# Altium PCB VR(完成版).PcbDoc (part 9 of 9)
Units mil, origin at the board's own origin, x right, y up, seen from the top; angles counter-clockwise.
Board outline 2839.68 x 2020.7 mil, 6 copper layers (TOP, GND02, SIN03, SIN04, PWR05, BOTTOM); 494 components, 404 nets, 7124 pads, 1123 vias.
Unrouted connection lines stored in the file: 10.
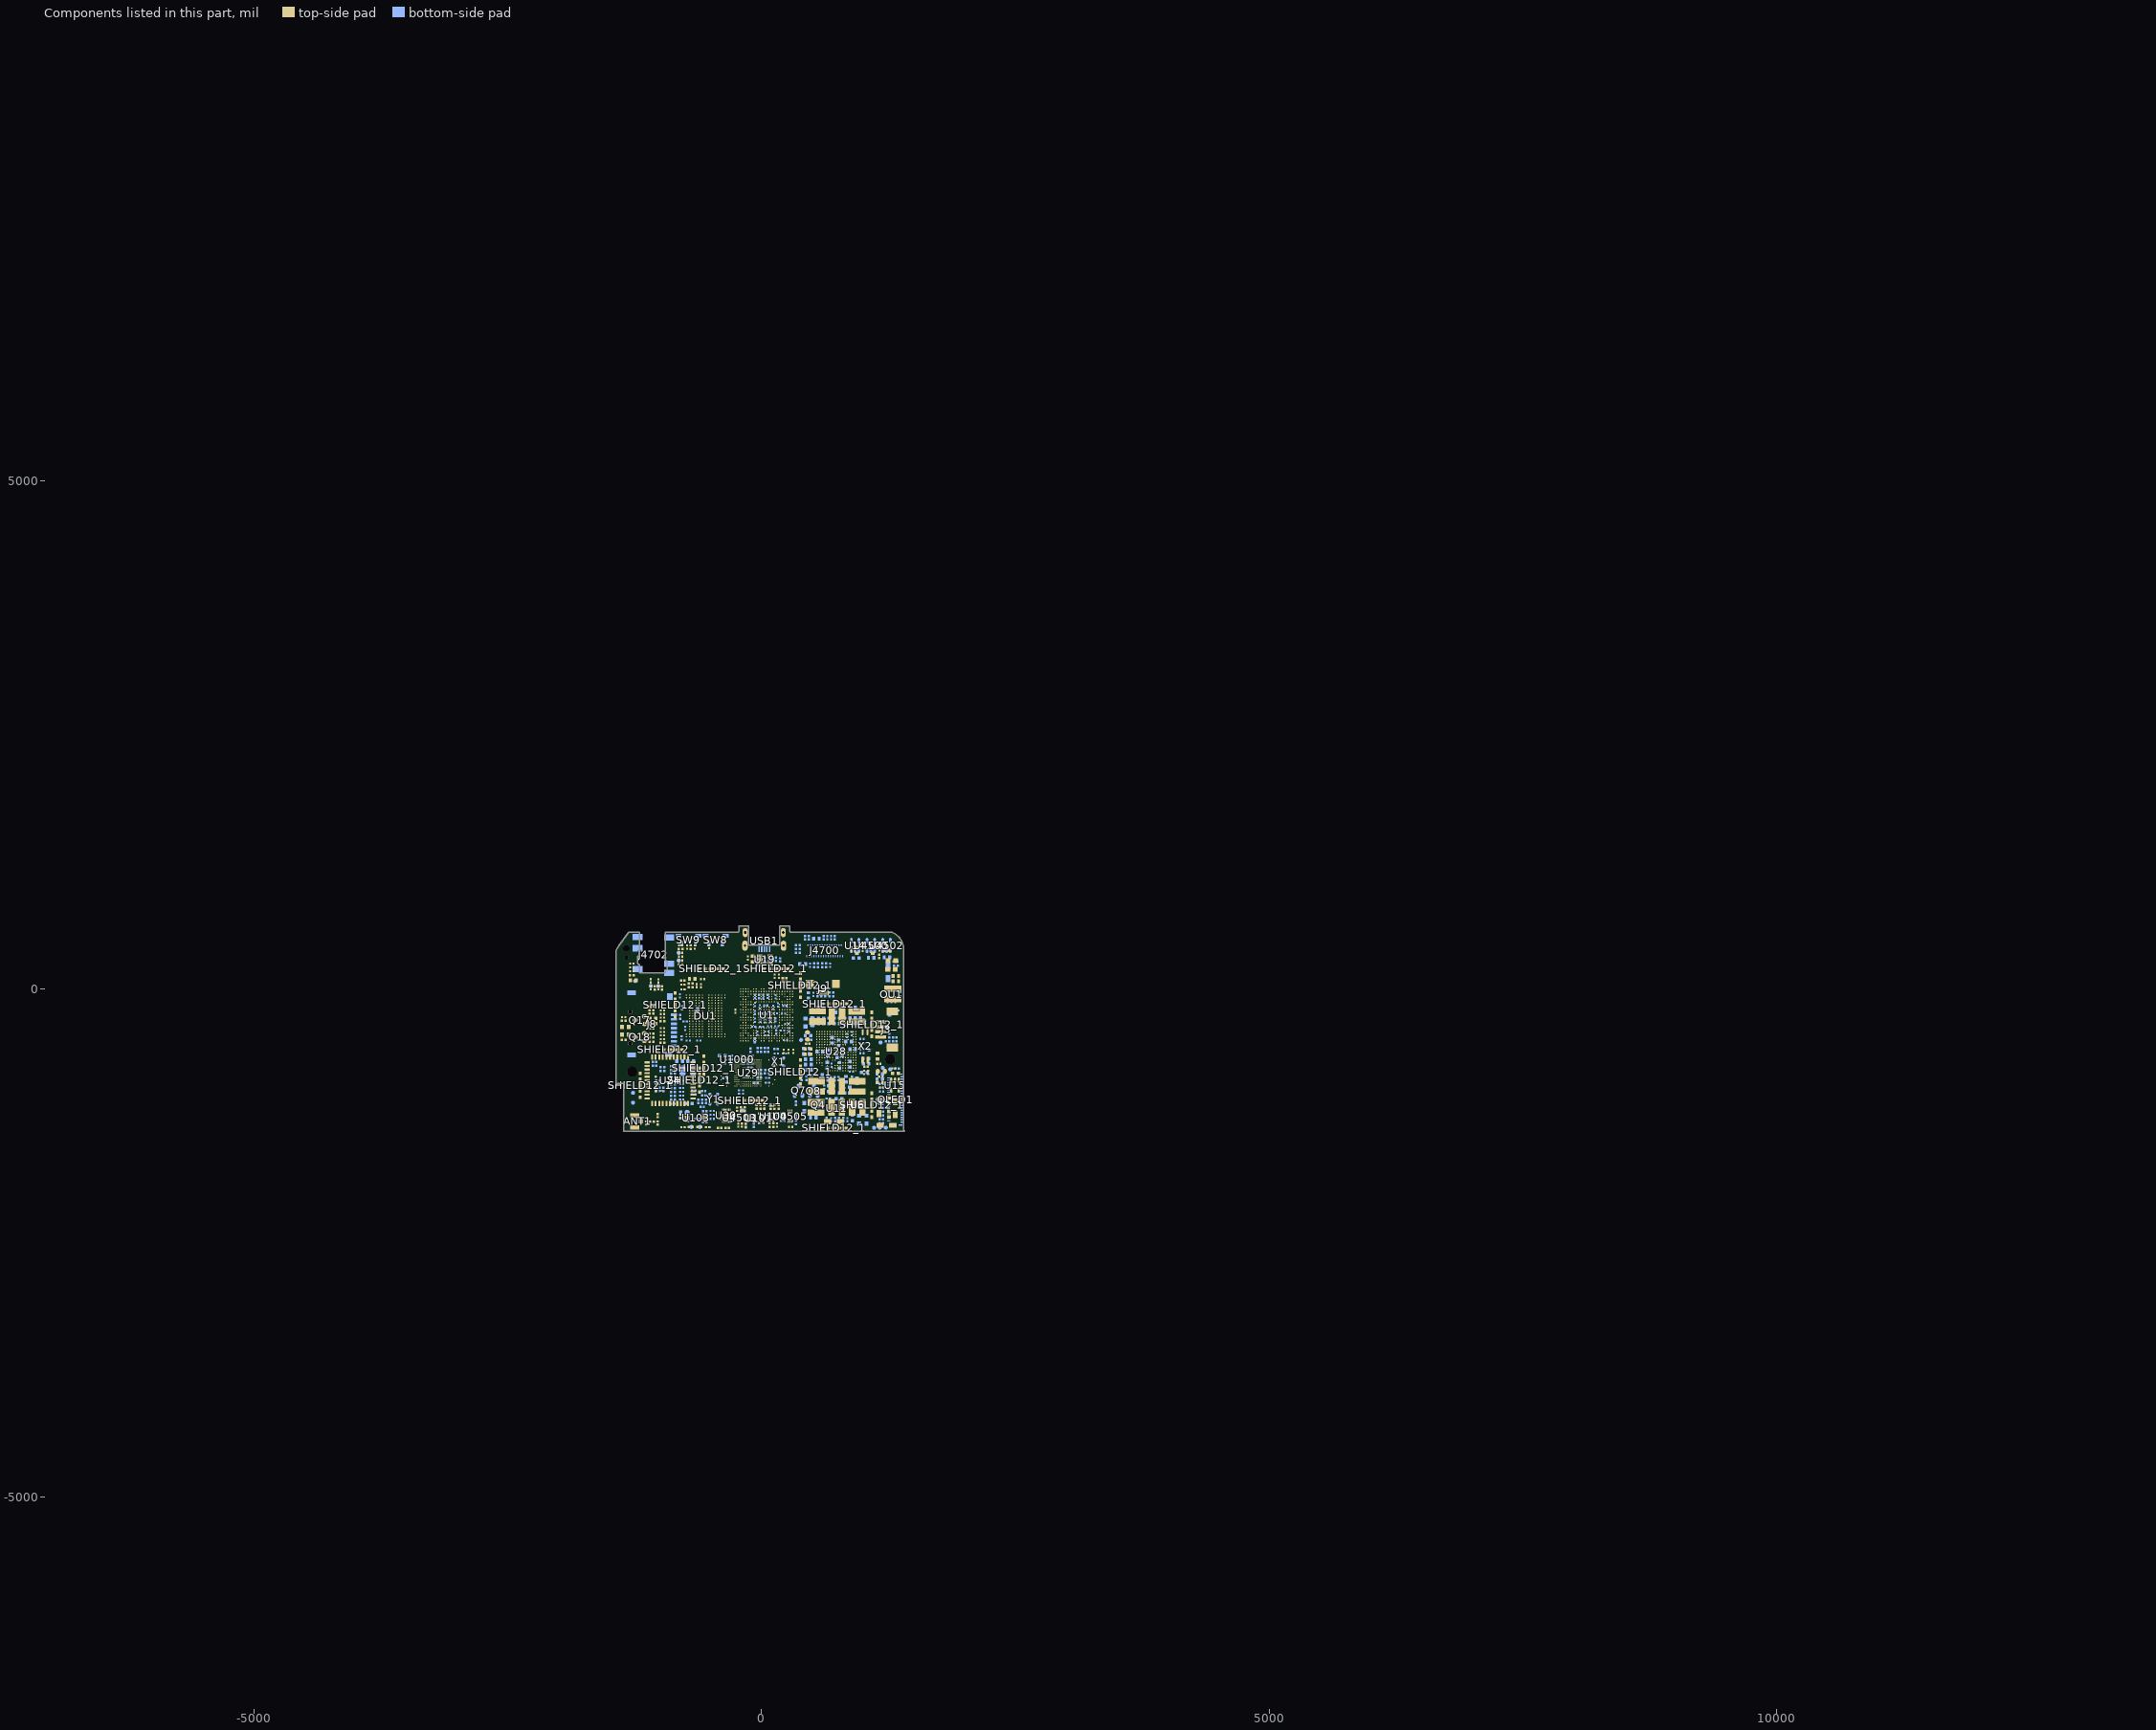
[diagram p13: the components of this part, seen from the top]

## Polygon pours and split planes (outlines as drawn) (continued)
VBAT on BOTTOM "Top Layer-No Net" (hatched 90Degree grid 4 track 5, remove dead copper, pour order 1004): -862,-1364 -862,-1199 -900,-1199 -927,-1172 -927,-1056.59 -924.27,-1053.86 -954.13,-1024 -1143,-1024 -1208.14,-958.86 -1303,-958.86 -1303,-1067 -994,-1067 -965,-1096 -965,-1329 -930,-1364
VBAT on BOTTOM "Top Layer-No Net" (hatched 90Degree grid 4 track 5, remove dead copper, pour order 1002): -1236,-1048 -1236,-954 -1251,-954 -1308,-954 -1308,-1002 -1308,-1048 -1236,-1048
USBVBUS on BOTTOM "Top Layer-No Net" (hatched 90Degree grid 4 track 5, remove dead copper, pour order 1006): 425,-346.86 524.73,-346.86 524.73,-399.15 545.73,-420.15 545.73,-437.86 544.73,-437.86 536.73,-445.86 460.86,-445.86 425,-410
GND on BOTTOM "Top Layer-No Net" (hatched 90Degree grid 4 track 5, remove dead copper, pour order 1003): 17 vertices, not listed, extent 490,-318.86 1046.73,-193.86
VCC_TP on BOTTOM "Top Layer-No Net" (hatched 90Degree grid 4 track 5, remove dead copper, pour order 1013): 456.73,16.14 518.73,16.14 518.73,-31.86 518.73,-44.86 462.73,-44.86 456.73,-44.86 456.73,16.14
DCDC1 on BOTTOM "Top Layer-No Net" (hatched 90Degree grid 4 track 5, remove dead copper, pour order 1012): 406.73,39.14 406.73,85.14 425.73,85.14 474.73,85.14 474.73,48.14 474.73,39.14 406.73,39.14
USB-5V on BOTTOM "Top Layer-No Net" (hatched 90Degree grid 4 track 5, remove dead copper, pour order 1011): 1229.73,256.14 1333.73,256.14 1333.73,217.14 1333.73,40.14 1301.73,40.14 1286.73,40.14 1286.73,53.14 1286.73,164.14 1264.73,164.14 1229.73,164.14 1229.73,256.14
N21149589 on BOTTOM "Top Layer-No Net" (hatched 90Degree grid 4 track 5, remove dead copper, pour order 1010): 1222.73,-14.86 1222.73,114.14 1251.73,114.14 1271.73,114.14 1271.73,14.14 1271.73,-14.86 1222.73,-14.86
VCC15_DVP on BOTTOM "Top Layer-No Net" (hatched 90Degree grid 4 track 5, remove dead copper, pour order 1008): 1277.23,496.14 1237.23,496.14 1237.23,478.14 1237.23,458.14 1271.23,458.14 1277.23,458.14 1277.23,496.14
VCC28_DVP on BOTTOM "Top Layer-No Net" (hatched 90Degree grid 4 track 5, remove dead copper, pour order 1007): 1122.73,496.14 1082.73,496.14 1082.73,478.14 1082.73,458.14 1116.73,458.14 1122.73,458.14 1122.73,496.14
VCC18_DVP on BOTTOM "Top Layer-No Net" (hatched 90Degree grid 4 track 5, remove dead copper, pour order 1006): 968.73,492.14 928.73,492.14 928.73,474.14 928.73,454.14 962.73,454.14 968.73,454.14 968.73,492.14
DCDC1 on BOTTOM "Top Layer-No Net" (hatched 90Degree grid 4 track 5, remove dead copper, pour order 1005): 1253.73,392.58 1311.73,392.58 1311.73,354.58 1311.73,296.58 1266.73,296.58 1253.73,296.58 1253.73,392.58
DCDC1 on BOTTOM "Top Layer-No Net" (hatched 90Degree grid 4 track 5, remove dead copper, pour order 1004): 1098.73,388.14 1156.73,388.14 1156.73,350.14 1156.73,292.14 1111.73,292.14 1098.73,292.14 1098.73,388.14
DCDC1 on BOTTOM "Top Layer-No Net" (hatched 90Degree grid 4 track 5, remove dead copper, pour order 1003): 952.73,388.14 1010.73,388.14 1010.73,350.14 1010.73,292.14 965.73,292.14 952.73,292.14 952.73,388.14
GND on BOTTOM "Top Layer-No Net" (hatched 90Degree grid 4 track 5, remove dead copper, pour order 1002): 78.73,412.14 238.73,412.14 238.73,375.14 238.73,355.14 91.73,355.14 74.73,355.14 74.73,399.14 74.73,412.14 78.73,412.14
USBVBUS on BOTTOM "Top Layer-No Net" (hatched 90Degree grid 4 track 5, remove dead copper, pour order 1001): -18.27,413.14 -126.27,413.14 -126.27,302.14 -18.27,302.14
N21107518 on BOTTOM "Top Layer-No Net" (hatched 90Degree grid 4 track 5, remove dead copper, pour order 1000): 18 vertices, not listed, extent -1049.27,-406.86 -832.27,-337.86
BB-VBAT on BOTTOM "Top Layer-No Net" (hatched 90Degree grid 4 track 5, remove dead copper, pour order 1010): -809.27,-1145.86 -790.27,-1126.86 -752.27,-1126.86 -734.27,-1126.86 -734.27,-1140.86 -734.27,-1165.86 -794.27,-1165.86 -809.27,-1165.86 -809.27,-1145.86
N17860913 on BOTTOM "Top Layer-No Net" (hatched 90Degree grid 4 track 5, remove dead copper, pour order 1009): -664.27,-816.86 -725.27,-816.86 -725.27,-784.86 -725.27,-747.86 -709.27,-747.86 -660.27,-747.86 -660.27,-777.86 -660.27,-816.86 -664.27,-816.86
N17861416 on BOTTOM "Top Layer-No Net" (hatched 90Degree grid 4 track 5, remove dead copper, pour order 1008): -794.27,-697.86 -794.27,-818.86 -776.27,-818.86 -754.27,-818.86 -754.27,-758.86 -754.27,-697.86 -794.27,-697.86
PS on BOTTOM "Top Layer-No Net" (hatched 90Degree grid 4 track 5, remove dead copper, pour order 1007): -781.27,-1260.86 -854.27,-1260.86 -854.27,-1279.86 -854.27,-1307.86 -827.27,-1307.86 -781.27,-1307.86 -781.27,-1260.86
N22437840 on BOTTOM "Top Layer-No Net" (hatched 90Degree grid 4 track 5, remove dead copper, pour order 1006): -660.27,-1265.86 -660.27,-1206.86 -682.27,-1206.86 -812.27,-1206.86 -812.27,-1217.86 -812.27,-1227.86 -716.27,-1227.86 -703.27,-1227.86 -703.27,-1258.86 -703.27,-1265.86 -660.27,-1265.86
DCDC1 on BOTTOM "Top Layer-No Net" (hatched 90Degree grid 4 track 5, remove dead copper, pour order 1005): 295.73,-1268.86 348.73,-1268.86 348.73,-1291.86 348.73,-1307.86 335.73,-1307.86 295.73,-1307.86 295.73,-1268.86
PS on BOTTOM "Top Layer-No Net" (hatched 90Degree grid 4 track 5, remove dead copper, pour order 1005): 675.73,-487.86 720.73,-487.86 720.73,-365.86 694.73,-365.86 694.73,-332.86 596.73,-332.86 596.73,-361.86 637.73,-361.86 675.73,-399.86
VDD-CPUB on BOTTOM "Top Layer-No Net" (hatched 90Degree grid 4 track 5, remove dead copper, pour order 1001): 745.73,-206.86 745.73,-177.86 662.73,-177.86 645.73,-177.86 645.73,-243.86 645.73,-261.86 723.73,-261.86 745.73,-261.86 745.73,-206.86
GND on BOTTOM "Top Layer-No Net" (hatched 90Degree grid 4 track 5, remove dead copper, pour order 1007): 447.73,-803.86 447.73,-530.86 423.73,-530.86 403.73,-530.86 403.73,-559.86 403.73,-813.86 435.73,-813.86 447.73,-813.86 447.73,-803.86
PS on BOTTOM "Top Layer-No Net" (hatched 90Degree grid 4 track 5, remove dead copper, pour order 1004): 526.73,-578.86 567.73,-578.86 567.73,-595.86 567.73,-632.86 545.73,-632.86 526.73,-632.86 526.73,-578.86
GND on BOTTOM "Top Layer-No Net" (hatched 90Degree grid 4 track 5, remove dead copper, pour order 1003): 835.73,-896.86 895.73,-896.86 895.73,-919.86 895.73,-984.86 872.73,-984.86 799.73,-984.86 799.73,-937.86 799.73,-918.86 820.73,-918.86 835.73,-918.86 835.73,-896.86
N21179643 on BOTTOM "Top Layer-No Net" (hatched 90Degree grid 4 track 5, remove dead copper, pour order 1002): 902.73,-807.86 890.41,-807.86 890.41,-866.86 890.41,-884.86 948.73,-884.86 957.73,-884.86 957.73,-858.86 957.73,-838.86 933.73,-838.86 926.73,-838.86 926.73,-821.86 926.73,-807.86 902.73,-807.86
N21179643 on BOTTOM "Top Layer-No Net" (hatched 90Degree grid 4 track 5, remove dead copper, pour order 1001): 856.73,-697.86 905.73,-697.86 905.73,-748.86 856.73,-748.86
VLED- on BOTTOM "Top Layer-No Net" (hatched 90Degree grid 4 track 5, remove dead copper, pour order 1001): 1198.73,-942.86 1198.73,-911.86 1238.73,-911.86 1272.73,-911.86 1284.73,-899.86 1290.73,-893.86 1353.73,-893.86 1382.73,-893.86 1382.73,-911.69 1382.73,-918.86 1358.73,-918.86 1297.73,-918.86 1283.73,-932.86 1273.73,-942.86 1198.73,-942.86
LCD_-V50AP on BOTTOM "Top Layer-No Net" (hatched 90Degree grid 4 track 5, remove dead copper, pour order 1000): 1382.73,-975.86 1312.73,-975.86 1312.73,-987.86 1312.73,-997.86 1345.73,-997.86 1382.73,-997.86 1382.73,-975.86
GND on BOTTOM "Top Layer-No Net" (hatched 90Degree grid 4 track 5, remove dead copper, pour order 1000): 1149.73,-899.86 1149.73,-785.86 1112.73,-785.86 1105.73,-785.86 1105.73,-829.86 1105.73,-899.86 1149.73,-899.86
VLED- on BOTTOM "Top Layer-No Net" (hatched 90Degree grid 4 track 5, remove dead copper, pour order 1001): 1188.73,-773.86 1218.73,-773.86 1218.73,-872.86 1218.73,-938.86 1209.73,-938.86 1188.73,-938.86 1188.73,-773.86
N21042265 on BOTTOM "Top Layer-No Net" (hatched 90Degree grid 4 track 5, remove dead copper, pour order 1002): 1167.73,-924.86 1115.73,-924.86 1115.73,-954.86 1115.73,-1010.86 1130.73,-1010.86 1141.73,-1010.86 1141.73,-978.86 1141.73,-947.86 1165.73,-947.86 1167.73,-947.86 1167.73,-924.86
LCD_+V50AP on BOTTOM "Top Layer-No Net" (hatched 90Degree grid 4 track 5, remove dead copper, pour order 1003): 1105.73,-1071.86 1164.73,-1071.86 1164.73,-1140.86 1105.73,-1140.86
DC1-SW on BOTTOM "Top Layer-No Net" (hatched 90Degree grid 4 track 5, remove dead copper, pour order 1004): 859.73,-1256.86 859.73,-1090.86 924.73,-1090.86 924.73,-1256.86
N22015419 on BOTTOM "Top Layer-No Net" (hatched 90Degree grid 4 track 5, remove dead copper, pour order 1005): 978.73,-1105.86 978.73,-1064.86 1003.73,-1064.86 1054.73,-1064.86 1054.73,-1106.86 1054.73,-1112.86 989.73,-1112.86 978.73,-1112.86 978.73,-1105.86
N21042253 on BOTTOM "Top Layer-No Net" (hatched 90Degree grid 4 track 5, remove dead copper, pour order 1006): 760.73,-1109.86 836.73,-1109.86 836.73,-1153.86 760.73,-1153.86
PS on BOTTOM "Top Layer-No Net" (hatched 90Degree grid 4 track 5, remove dead copper, pour order 1007): 664.73,-1068.86 744.73,-1068.86 744.73,-1090.86 744.73,-1110.86 730.73,-1110.86 719.73,-1110.86 719.73,-1134.86 719.73,-1149.86 690.73,-1149.86 664.73,-1149.86 664.73,-1068.86
VLED+ on BOTTOM "Top Layer-No Net" (hatched 90Degree grid 4 track 5, remove dead copper, pour order 1008): 666.73,-1160.86 752.73,-1160.86 752.73,-1181.86 752.73,-1194.86 728.73,-1194.86 666.73,-1194.86 666.73,-1160.86
DCDC1 on BOTTOM "Top Layer-No Net" (hatched 90Degree grid 4 track 5, remove dead copper, pour order 1009): 857.01,-1012.86 966.73,-1012.86 966.73,-1055.86 857.01,-1055.86
BB-VBAT on BOTTOM "Top Layer-No Net" (hatched 90Degree grid 4 track 5, remove dead copper, pour order 1010): 18 vertices, not listed, extent 408.73,-1151.86 616.73,-1085.86
PS on BOTTOM "Top Layer-No Net" (hatched 90Degree grid 4 track 5, remove dead copper, pour order 1011): 512.73,-1161.86 579.73,-1161.86 579.73,-1188.86 647.73,-1188.86 647.73,-1233.86 512.73,-1233.86
VBAT on BOTTOM "Top Layer-No Net" (hatched 90Degree grid 4 track 5, remove dead copper, pour order 1012): 404.73,-1189.86 404.73,-1294.86 500.73,-1294.86 500.73,-1189.86
VBAT on BOTTOM "Top Layer-No Net" (hatched 90Degree grid 4 track 5, remove dead copper, pour order 1013): 455.73,-1139.86 494.73,-1139.86 494.73,-1168.86 494.73,-1212.86 479.73,-1212.86 455.73,-1212.86 455.73,-1139.86
VCC-DRAM on BOTTOM "Top Layer-No Net" (hatched 90Degree grid 4 track 5, remove dead copper, pour order 1014): 637.73,-983.86 654.73,-1000.86 721,-1000.86 721,-1049 593.73,-1049 593.73,-983.86
VDD-CPUA on BOTTOM "Top Layer-No Net" (hatched 90Degree grid 4 track 5, remove dead copper, pour order 1000): 571.73,-168 492.73,-168 492.73,-256.86 571.73,-256.86
VDD-GPU on BOTTOM "Top Layer-No Net" (hatched 90Degree grid 4 track 5, remove dead copper, pour order 1002): 936.73,-219.86 936.73,-173 851.73,-173 851.73,-250.86 937.73,-250.86 937.73,-219.86
N21180774 on BOTTOM "Top Layer-No Net" (hatched 90Degree grid 4 track 5, remove dead copper, pour order 1004): 936.73,-655.86 1007,-655.86 1007,-753 936.73,-753
BB-VBAT on BOTTOM "Top Layer-No Net" (hatched 90Degree grid 4 track 5, remove dead copper, pour order 1000): 403,-1118 450,-1118 450,-1147 450,-1172 424,-1172 403,-1172 403,-1118
VDD-CPUA on BOTTOM "Top Layer-No Net" (hatched 90Degree grid 4 track 5, remove dead copper, pour order 1001): 22 vertices, not listed, extent -20,-303 121,-197
N21179643 on BOTTOM "TopLayer-No Net" (hatched 90Degree grid 4 track 5, remove dead copper, pour order 1000): 879,-702.86 904.86,-702.86 933,-731 955.73,-753.73 955.73,-869 890.41,-869 890.41,-856 890.41,-770 887,-770 879,-762 879,-702.86
GND on BOTTOM "Top Layer-No Net" (hatched 90Degree grid 4 track 5, remove dead copper, pour order 1003): -1304,-1082 -1237,-1082 -1237,-1114 -1237,-1154 -1275,-1154 -1304,-1154 -1304,-1082
DC1-SW on TOP "Top Layer-No Net" (hatched 90Degree grid 4 track 5, remove dead copper, pour order 1023): 1341,-670.86 1379.73,-670.86 1379.73,-866.86 1341,-866.86
DC1-SW on TOP "Top Layer-No Net" (hatched 90Degree grid 4 track 5, remove dead copper, pour order 1010): 1180,-677.86 1180,-605 1220,-605 1220,-705 1127,-705 1127,-677.86
N21149589 on TOP "Top Layer-No Net" (hatched 90Degree grid 4 track 5, remove dead copper, pour order 1022): 1274.73,102 1274.73,-2.86 1213.73,-2.86 1213.73,102
BB-VBAT on TOP "TopLayer-No Net" (hatched 90Degree grid 4 track 5, remove dead copper, pour order 1006): -771,-1109.54 -771,-1163 -822,-1163 -822,-1109.54
VDD-GPU on TOP "Top Layer-No Net" (hatched 90Degree grid 4 track 5, remove dead copper, pour order 1001): 839,-184 931,-184 931,-201 931,-239 893,-239 839,-239 839,-184
GND on TOP "Top Layer-No Net" (hatched 90Degree grid 4 track 5, remove dead copper, pour order 1000): -121.13,287.14 -166,287.14 -166,340 -237,340 -237,258 -104.27,258 -104.27,276
DCIN on TOP "Top Layer-No Net" (hatched 90Degree grid 4 track 5, remove dead copper, pour order 1011): 524.73,-477.86 442.73,-395.86 442.73,-292 406.73,-292 406.73,-425.86 485.73,-504.86 572.27,-504.86 572.27,-477.86
LCD_+V50AP on TOP "Top Layer-No Net" (hatched 90Degree grid 4 track 5, remove dead copper, pour order 1015): 1202,-1035 1114,-1035 1114,-1122 1202,-1122
BB-VBAT on TOP "Top Layer-No Net" (hatched 90Degree grid 4 track 5, remove dead copper, pour order 1003): 469,-625 469,-785 411,-843 411,-1243 593,-1243 593,-1172 457,-1172 457,-883 506,-834 506,-625
PS on TOP "Top Layer-No Net" (hatched 90Degree grid 4 track 5, remove dead copper, pour order 1009): 1237,-84 1297,-84 1297,-131 1297,-179 1268,-179 1237,-179 1237,-84
VLED+ on TOP "Top Layer-No Net" (hatched 90Degree grid 4 track 5, remove dead copper, pour order 1008): 18 vertices, not listed, extent 619,-1331 762,-1156
PS on TOP "Top Layer-No Net" (hatched 90Degree grid 4 track 5, remove dead copper, pour order 1007): 654,-1085 712,-1085 712,-1170 712,-1243 657,-1243 632,-1243 632,-1196 632,-1085 654,-1085
N21042253 on TOP "Top Layer-No Net" (hatched 90Degree grid 4 track 5, remove dead copper, pour order 1006): 772,-1212 820,-1212 820,-1230 820,-1324 788,-1324 772,-1324 772,-1212
BB-VBAT on TOP "Top Layer-No Net" (hatched 90Degree grid 4 track 5, remove dead copper, pour order 1012): 557.73,-541.86 521.73,-541.86 477.73,-585.86 478.73,-585.86 493.73,-600.86 503.73,-600.86 503.73,-599.27 543,-560 557.73,-560
ALDO2 on TOP "Top Layer-No Net" (hatched 90Degree grid 4 track 5, remove dead copper, pour order 1000): -674.99,-62.3 -674.99,-31 -661,-31 -610,-31 -610,16 -610,22 -591,22 -574,22 -574,-42 -574,-69 -668,-69 -674.99,-69 -674.99,-62.3
N21232804 on TOP "Top Layer-No Net" (hatched 90Degree grid 4 track 5, remove dead copper, pour order 1002): 879,-307 977,-307 977,-346 977,-367 948,-396 940,-404 886,-404 879,-404 879,-307
N21231924 on TOP "Top Layer-No Net" (hatched 90Degree grid 4 track 5, remove dead copper, pour order 1001): 774,-291 826,-291 826,-332 826,-406 773,-406 754,-387 754,-383 754,-311 774,-291
N21230780 on TOP "Top Layer-No Net" (hatched 90Degree grid 4 track 5, remove dead copper, pour order 1000): 649.04,-446.69 649.04,-329.04 633,-313 536,-313 536,-320 624,-408 624,-429 624,-446.69 649.04,-446.69
VCC_TP on TOP "Top Layer-No Net" (hatched 90Degree grid 4 track 5, remove dead copper, pour order 1025): 461.73,-2.86 528.73,-2.86 528.73,-18.86 528.73,-42.86 477.73,-42.86 461.73,-42.86 461.73,-2.86
GND on TOP "Top Layer-No Net" (hatched 90Degree grid 4 track 5, remove dead copper, pour order 1024): 1332.73,147.14 1377.73,147.14 1377.73,44.14 1332.73,44.14
USB-5V on TOP "Top Layer-No Net" (hatched 90Degree grid 4 track 5, remove dead copper, pour order 1023): 1277.73,147.14 1321.73,147.14 1321.73,62.14 1321.73,36.14 1292.73,36.14 1273.73,36.14 1273.73,139.14 1273.73,147.14 1277.73,147.14
VCC15_DVP on TOP "Top Layer-No Net" (hatched 90Degree grid 4 track 5, remove dead copper, pour order 1021): 1248.73,370.14 1234.73,370.14 1234.73,488.14 1234.73,501.14 1255.73,501.14 1287.73,501.14 1287.73,379.14 1287.73,370.14 1248.73,370.14
VCC28_DVP on TOP "Top Layer-No Net" (hatched 90Degree grid 4 track 5, remove dead copper, pour order 1020): 1081.73,397.14 1081.73,493.14 1106.73,493.14 1124.73,493.14 1124.73,431.14 1124.73,397.14 1081.73,397.14
VCC18_DVP on TOP "Top Layer-No Net" (hatched 90Degree grid 4 track 5, remove dead copper, pour order 1019): 927.73,396.14 927.73,494.14 937.73,494.14 957.73,494.14 957.73,452.14 957.73,396.14 927.73,396.14
GND on TOP "Top Layer-No Net" (hatched 90Degree grid 4 track 5, remove dead copper, pour order 1018): -142.27,287.14 -73.27,287.14 -73.27,254.14 -73.27,232.14 -146.27,232.14 -157.27,232.14 -157.27,260.14 -157.27,287.14 -142.27,287.14
USB-5V on TOP "Top Layer-No Net" (hatched 90Degree grid 4 track 5, remove dead copper, pour order 1017): 69.73,322.14 69.73,383.14 97.73,383.14 232.73,383.14 232.73,299.14 232.73,292.14 164.73,292.14 69.73,292.14 69.73,322.14
USBVBUS on TOP "Top Layer-No Net" (hatched 90Degree grid 4 track 5, remove dead copper, pour order 1016): -136.27,312.14 -136.27,388.14 -97.27,388.14 3.73,388.14 3.73,327.14 3.73,312.14 -136.27,312.14
DCDC1 on TOP "Top Layer-No Net" (hatched 90Degree grid 4 track 5, remove dead copper, pour order 1015): -1081.27,-274.86 -1156.27,-274.86 -1156.27,-295.86 -1156.27,-317.86 -1139.27,-317.86 -1072.27,-317.86 -1072.27,-311.86 -1072.27,-274.86 -1081.27,-274.86
N21107518 on TOP "Top Layer-No Net" (hatched 90Degree grid 4 track 5, remove dead copper, pour order 1014): -1055.27,-279.86 -1019.27,-279.86 -1019.27,-298.86 -1019.27,-404.86 -1053.27,-404.86 -1068.27,-404.86 -1068.27,-387.86 -1068.27,-370.86 -1055.27,-370.86 -1055.27,-279.86
N17861416 on TOP "Top Layer-No Net" (hatched 90Degree grid 4 track 5, remove dead copper, pour order 1015): 18 vertices, not listed, extent -795.27,-775.86 -711.27,-665.86
N17860913 on TOP "Top Layer-No Net" (hatched 90Degree grid 4 track 5, remove dead copper, pour order 1014): -667.27,-750.86 -730.27,-750.86 -730.27,-770.86 -730.27,-785.86 -709.27,-785.86 -688.27,-785.86 -688.27,-774.86 -667.27,-774.86 -667.27,-750.86
PS on TOP "Top Layer-No Net" (hatched 90Degree grid 4 track 5, remove dead copper, pour order 1013): -793.27,-1262.86 -853.27,-1262.86 -853.27,-1289.86 -853.27,-1305.86 -815.27,-1305.86 -793.27,-1305.86 -793.27,-1262.86
VDD-CPUB on TOP "Top Layer-No Net" (hatched 90Degree grid 4 track 5, remove dead copper, pour order 1012): 646.73,-181.86 697.73,-181.86 697.73,-200.86 697.73,-257.86 655.73,-257.86 646.73,-257.86 646.73,-184.86
VDD-CPUA on TOP "Top Layer-No Net" (hatched 90Degree grid 4 track 5, remove dead copper, pour order 1011): 486.73,-211.86 568.73,-211.86 568.73,-248.86 568.73,-267.86 543.73,-267.86 485.73,-267.86 485.73,-211.86
GND on TOP "Top Layer-No Net" (hatched 90Degree grid 4 track 5, remove dead copper, pour order 1014): 451.73,-534.86 404.73,-534.86 404.73,-570.86 404.73,-729.86 438.73,-729.86 450.73,-729.86 450.73,-692.86 450.73,-534.86 451.73,-534.86
BB-VBAT on TOP "Top Layer-No Net" (hatched 90Degree grid 4 track 5, remove dead copper, pour order 1013): 470.73,-574.86 503.73,-574.86 503.73,-600.86 503.73,-654.86 479.73,-654.86 470.73,-654.86 470.73,-574.86
N21229926 on TOP "Top Layer-No Net" (hatched 90Degree grid 4 track 5, remove dead copper, pour order 1009): 978.73,-881.86 1046.73,-881.86 1046.73,-913.86 1046.73,-934.86 1019.73,-934.86 978.73,-934.86 978.73,-881.86
DCDC6 on TOP "Top Layer-No Net" (hatched 90Degree grid 4 track 5, remove dead copper, pour order 1008): 742.73,-945.86 804.73,-945.86 804.73,-974.86 804.73,-1019.86 764.73,-1019.86 733.73,-1019.86 733.73,-963.86 733.73,-945.86 742.73,-945.86
N21233778 on TOP "Top Layer-No Net" (hatched 90Degree grid 4 track 5, remove dead copper, pour order 1027): 624.73,-722.86 664.73,-722.86 664.73,-834.86 712.73,-834.86 712.73,-901.86 665.73,-901.86 624.73,-860.86
N22015419 on TOP "Top Layer-No Net" (hatched Horizontal grid 4 track 5, remove dead copper, pour order 1016): 1277.73,-1167.86 1112.73,-1167.86 1112.73,-1219.86 1277.73,-1219.86
N22015421 on TOP "Top Layer-No Net" (hatched 90Degree grid 4 track 5, remove dead copper, pour order 1017): 1246.73,-1262.86 1246.73,-1343.86 1294.73,-1343.86 1321.73,-1343.86 1321.73,-1265.86 1321.73,-1249.86 1247.73,-1249.86 1246.73,-1249.86 1246.73,-1262.86
DC1-SW on TOP "Top Layer-No Net" (hatched 90Degree grid 4 track 5, remove dead copper, pour order 1018): 1338.73,-824.86 1374.73,-824.86 1374.73,-844.86 1374.73,-917.86 1356.73,-917.86 1338.73,-917.86 1338.73,-824.86
LCD_-V50AP on TOP "Top Layer-No Net" (hatched 90Degree grid 4 track 5, remove dead copper, pour order 1019): 1244.73,-1055.86 1315.73,-1055.86 1315.73,-977.86 1344.73,-977.86 1344.73,-1088.86 1244.73,-1088.86
LCDIO on TOP "Top Layer-No Net" (hatched 90Degree grid 4 track 5, remove dead copper, pour order 1020): 1363.73,-1002.86 1363.73,-924.86 1315.73,-924.86 1251.73,-924.86 1251.73,-911.86 1251.73,-908.86 1208.73,-908.86 1184.73,-908.86 1184.73,-917.86 1209.73,-942.86 1209.73,-973.86 1336.73,-973.86 1336.73,-999.86 1336.73,-1002.86 1363.73,-1002.86
GND on TOP "Top Layer-No Net" (hatched 90Degree grid 4 track 5, remove dead copper, pour order 1021): 1162.73,-975.86 1106.73,-975.86 1106.73,-789.86 1162.73,-789.86
VLED+ on TOP "Top Layer-No Net" (hatched 90Degree grid 4 track 5, remove dead copper, pour order 1022): 1296.73,-778.86 1203.73,-778.86 1203.73,-834.86 1245.73,-834.86 1245.73,-810.86 1296.73,-810.86
DC1-SW on TOP "Top Layer-No Net" (hatched 90Degree grid 4 track 5, remove dead copper, pour order 1024): 1152.73,-677.86 1121.76,-677.86 1121.76,-731.86 1121.76,-751.86 1145.73,-751.86 1152.73,-751.86 1152.73,-677.86
N22015419 on TOP "Top Layer-No Net" (hatched 90Degree grid 4 track 5, remove dead copper, pour order 1025): 980.73,-1105.86 980.73,-1060.86 1012.73,-1060.86 1055.73,-1060.86 1055.73,-1097.86 1055.73,-1115.86 1002.73,-1115.86 980.73,-1115.86 980.73,-1105.86
N21233685 on TOP "Top Layer-No Net" (hatched 90Degree grid 4 track 5, remove dead copper, pour order 1026): 603.73,-723.86 580.73,-723.86 566.73,-737.86 528.73,-775.86 528.73,-875.86 528.73,-917.86 570.73,-917.86 603.73,-917.86 603.73,-723.86
USBVBUS on TOP "Top Layer-No Net" (hatched 90Degree grid 4 track 5, remove dead copper, pour order 1010): 450,-376 520,-376 552.73,-408.73 552.73,-450.86 524.86,-450.86
VDD-CPUA on SIN03 "Top Layer-No Net" (hatched 90Degree grid 4 track 5, remove dead copper, pour order 1013): 555,-255 555,-137 -33,-137 -33,-285 4,-322 488,-322
DC1-SW on SIN03 "Top Layer-No Net" (hatched 90Degree grid 4 track 5, remove dead copper, pour order 1003): 18 vertices, not listed, extent 1198,-859 1388,-577
DC1-SW on SIN03 "Top Layer-No Net" (hatched 90Degree grid 4 track 5, remove dead copper, pour order 1002): 1219,-571 1331.03,-571 1331.03,-600.03 1331.03,-644 1209,-644 1209,-571 1219,-571
VBAT on SIN03 "Top Layer-No Net" (hatched 90Degree grid 4 track 5, remove dead copper, pour order 1011): 406,-1245 460,-1245 460,-1265 460,-1399.33 274,-1399.33 -932,-1399.33 -932,-1343 -932,-1321 -870,-1321 365,-1321 365,-1278 365,-1245 406,-1245
USB-5V on SIN03 "Top Layer-No Net" (hatched 90Degree grid 4 track 5, remove dead copper, pour order 1012): 1294,35 1371,35 1371,374 1295,450 317,450 250,383 125,383 125,324 299,324 368,393 1245.3,393 1292.73,345.58 1289,341.85 1289,40
DC1-SW on SIN03 "TopLayer-No Net" (hatched 90Degree grid 4 track 5, remove dead copper, pour order 1001): 851,-1090 924,-1090 1207.14,-806.86 1264,-806.86 1264,-844 940,-1168 851,-1168
N21231924 on SIN03 "TopLayer-No Net" (hatched 90Degree grid 4 track 5, remove dead copper, pour order 1002): 803,-361 803,-473 718,-473 718,-361
USBVBUS on SIN04 "Top Layer-No Net" (hatched 90Degree grid 4 track 5, remove dead copper, pour order 1005): -101,411 296,411 296,364 220,288 -112,288 -130,306 -130,382
DCDC6 on SIN04 "Top Layer-No Net" (hatched 90Degree grid 4 track 5, remove dead copper, pour order 1002): 128,-175 208,-175 208,-233 128,-233
N22015419 on SIN04 "Top Layer-No Net" (hatched 90Degree grid 4 track 5, remove dead copper, pour order 1006): 18 vertices, not listed, extent 982,-1217 1143,-1064
N21221879 on SIN04 "Top Layer-No Net" (hatched Horizontal grid 4 track 5, remove dead copper, pour order 1003): 594,-1099 474,-1099 435,-1060 435,-582 473,-544 559.48,-544 559.48,-592 514,-592 514,-1002 562,-1050 594,-1050
N21229926 on SIN04 "Top Layer-No Net" (hatched 90Degree grid 4 track 5, remove dead copper, pour order 1004): 838,-578 838,-518.5 874,-518.5 876.47,-517.47 915.95,-478 1056,-478 1056,-935 956,-935 956,-578
N21232804 on SIN04 "TopLayer-No Net" (hatched 90Degree grid 4 track 5, remove dead copper, pour order 1003): 897,-360 949,-360 966,-377 966,-430 896.05,-499.95 811,-499.95 811,-449 840,-449 885,-404 885,-372
PS on SIN04 "Top Layer-No Net" (hatched 90Degree grid 4 track 5, remove dead copper, pour order 1005): 18 vertices, not listed, extent 546.59,-1174.59 850.59,-402.59
GND on GND02 (split plane): 322 vertices, not listed, extent -1420.69,-1391.97 1391.43,608.95
DCDC1 on PWR05 (split plane): 427 vertices, not listed, extent -1400.68,-1371.96 1371.41,588.9
VCC-DRAM on PWR05 (split plane): 35 vertices, not listed, extent -816.9,-1062.9 681.9,180.9
BB-VBAT on PWR05 (split plane): 22 vertices, not listed, extent -835.9,-1184.9 484.9,-958.53
DCDC6 on PWR05 (split plane): 53 vertices, not listed, extent -71.9,-1062.9 798.9,-156.1
VDD-CPUB on PWR05 (split plane): 28 vertices, not listed, extent -71.9,-238.9 729.9,-47.1
VDD-GPU on PWR05 (split plane): 23 vertices, not listed, extent 31.1,-402.9 924.9,-141.1
PS on PWR05 (split plane): 21 vertices, not listed, extent 489.1,-503.9 1293.9,-141.1
no net on PWR05 (split plane): 49 vertices, not listed, extent 877.9,-130.9 1163.63,-111.58

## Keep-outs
Keep-Out Layer:
  lines w5: 1359.35,-1399.33 ccw(c1359.35,-1261.54) 1398.72,-1393.59 1398.72,-523.98 1398.72,-386.18 1398.72,389.68 ccw(c1221.55,389.68) 1289.19,553.42 296.35,553.42 cw(c296.35,573.11) 276.67,573.11 276.67,616.33 184.15,616.33 184.15,429.33 -126.87,429.33 -126.87,616.33 -219.39,616.33 -219.39,573.03 cw(c-239.08,573.03) -239.08,553.34 -943.8,553.34 -943.8,282.99 cw(c-949.71,260.12) -926.09,260.12 -926.09,185.31 -943.8,185.31 -943.8,155.79 -1201.68,155.79 -1201.68,236.82 cw(c-1197.74,260.12) -1221.36,260.12 -1221.36,323.11 -1201.68,323.11 -1201.68,553.34 -1307.34,553.34 ccw(c-1215.93,478.54) -1311.77,547.57 -1400.16,424.86 ccw(c-1144.59,240.78) -1428.06,378.07 -1428.06,-926.89 -1353.25,-926.89 -1353.25,-1399.33 -1077.66,-1399.33 796.35,-1399.33 1012.89,-1399.33 1406.59,-1399.33 ; 851.47,-81.49 ccw(c871.16,-81.49) 890.84,-81.49 1150.68,-81.49 ccw(c1170.37,-81.49) 1190.06,-81.49 1190.05,257.09 ccw(c1170.37,257.09) 1150.68,257.09 890.84,257.09 ccw(c871.16,257.09) 851.47,257.09 851.47,-81.49

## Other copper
TOP:
  rectangle net N21230780: 634,-446.69 649.04,-389
  pour cut-out: -189,-26 268.7,-26 268.7,-444 -196,-444 -196,-39.28
  pour cut-out: 901,-427 901,-738.86 700.23,-738.86 700.23,-689.81 553.09,-689.81 553.09,-427
  pour cut-out: 194.42,-1164 194.42,-1349 282,-1349 282,-1396 -49,-1396 -49,-1306.72 -297,-1306.72 -297,-1164
  pour cut-out: 1395,-1026 1395,-1064 1343.73,-1064 1343.73,-1026
  pour cut-out: 832,-880 858,-880 858,-953.24 1040.77,-953.24 1040.77,-978 861,-978 861,-1062.86 832,-1062.86
  pour cut-out: 966,-1043 966,-1266.86 924,-1266.86 924,-1082 858,-1082 858,-1263.22 831,-1263.22 831,-1084 518,-1084 518,-1043
  pour cut-out: 628,-897 658,-897 658,-967.61 549,-967.61 549,-947 628,-947
  pour cut-out: 487,-944 565,-944 565,-976 487,-976
  pour cut-out: 1024,-255 1024,-295 856.25,-295 856.25,-255
  pour cut-out: 663,-251.3 663,-288 568,-288 568,-251.3
  pour cut-out: 727,-317 747,-317 747,-384 727,-384
  pour cut-out: -461,-36 -190,-36 -190,-477 -486.01,-477 -486.01,-42 -444,-42
  text "TOP" at -1313.27,908.14 h60
SIN03:
  pour cut-out: 396,119 396,30 722.68,30 722.68,127 401,127
  pour cut-out: 65,106 65,26 -29,26 -29,106
  pour cut-out: 106,-322 254,-322 254,-427 106,-427
  pour cut-out: 840.98,-426 923,-426 923,-539 840.98,-539
  pour cut-out: 383,-742 668,-742 668,-841 383,-841
  pour cut-out: -66,-874.86 13.5,-874.86 13.5,-990.86 -66,-990.86
  text "SIN03" at -676.27,908.14 h60
SIN04:
  pour cut-out: 818,-909 909,-909 909,-1025 818,-1025
  pour cut-out: 518,-1123 518,-1311 331,-1311 331,-1365 -218,-1365 -218,-1310 -362,-1310 -362,-1123
  pour cut-out: -240.33,-610.33 -59,-610.33 -59,-936 -283.44,-936 -283.44,-871 -148,-871 -148,-731 -322,-731 -322,-810 -599.76,-810 -599.76,-672 -242.14,-672 -242.14,-612.14
  pour cut-out: 474.5,-190.51 474.5,-495 292,-495 292,-190.51
  text "SIN04" at -318.27,908.14 h60
BOTTOM:
  pour cut-out: -1042,-764 -813.6,-764 -813.6,-1006 -1042,-1006
  pour cut-out: 246,-1107.14 246,-1229 -35,-1229 -35,-1107.14
  pour cut-out: 848.42,-831.35 884,-831.35 884,-896.86 848.42,-896.86
  pour cut-out: -204.97,-48.02 -204.97,-493 -733.99,-493 -733.99,-296 -558.81,-296 -558.81,-128 -723,-128 -723,-48.02
  text "BOTTOM" at 915.73,908.14 h60
GND02 (plane layer: these items are gaps in the copper):
  text "GND02" at -1062.27,908.14 h60
PWR05 (plane layer: these items are gaps in the copper):
  lines w10: -77,-211 17,-211 46,-182 111,-182 142,-151 195,-151 217.52,-173.52 217.52,-220.48 194,-244 ; -25,-42 42,-42 735,-42 735,-205 696,-244 631,-244 194,-244 ; 343.32,-951.32 323.65,-971 -841,-971 -841,-1184 -681.15,-1184 -681.15,-1107 301,-1107 384,-1190 490,-1190 490,-1068 ; 484,-380 484,-472 521,-509 873,-509 928,-454 950,-454 1117,-287 1299,-287 1299,-136 1229,-136 930,-136 ; 735,-136 930,-136 ; 194,-244 165.45,-244 140.75,-268.7 55.3,-268.7 26,-298 26,-358 76,-408 240,-408 ; 240,-408 268,-380 819,-380 930,-269 930,-136 ; 240,-408 240,-442 535,-737 700,-737 804,-841 804,-1068 687,-1068 ; 687,-1068 687,-948 614,-875 494,-875 126,-507 -25,-507 -77,-455 -77,-172 -25,-120 -25,105 -106,186 -489,186 -516,159 -736,159 -822,73 -822,-538 -584,-538 -481,-641 -176,-641 33,-641 460,-1068 687,-1068
  text "PWR05" at 81.73,908.14 h60

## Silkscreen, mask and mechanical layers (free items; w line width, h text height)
Top Solder:
  lines w31.5: -1191.27,-1067 -1191.27,-1188.86 -1089,-1188.86 ; -1191.27,-831 -1191.27,-597.86 -1023,-597.86 ; -954,-1188.86 -607.27,-1188.86 -607.27,-1020 ; -847.27,-280 -847.27,-555.86 -566.27,-555.86 -566.27,-655 ; -847.27,-36 -847.27,109.14 -847.27,198.14 -616,198.14 ; -778,-597.86 -607.27,-597.86 -607.27,-778 ; -566.27,-904 -566.27,-1099.86 -265,-1099.86 ; -380,198 24,198.14 ; -255,-1099.86 56,-1099.86 ; 66,-1099.86 383.73,-1099.86 ; 262,198.14 384,198.14 384,156 ; 383.73,-934 383.73,-1369.86 593,-1369.86 ; 383.73,-702 383.73,-146.86 601,-146.86 ; 383.73,-198.86 383.73,-80 ; 840,-1369.86 1087.73,-1369.86 1087.73,-1260 ; 845,-146.86 1087.73,-146.86 1087.73,-233 ; 1085.73,-479 1087,-1026
Mechanical 4:
  drawing of 2527 lines, arcs and shapes, not listed
Mechanical 5:
  drawing of 1201 lines, arcs and shapes, not listed
Drill Drawing:
  drawing of 2472 lines, arcs and shapes, not listed
  text "Purchase   Order &  Specification   Sheet" at 7441.15,7648.63 h77.51
  text "1.6" at 8973.62,7529.73 h38.75
  text "6" at 10232.59,7528.26 h38.75
  text "Dielectric Material:" at 6552.34,7522.87 h38.75
  text "IT180A" at 7559.4,7519.49 h38.75
  text "Board Thickness(MM):" at 8050.87,7519.45 h38.75
  text "Layers:" at 9431.19,7519.45 h38.75
  text "Osp" at 10347.33,7319.06 h38.75
  text "Surface Finished:" at 6553.9,7316.19 h38.75
  text "Gold Finger" at 9621.76,7316.5 h38.75
  text "Flash Gold" at 8225.49,7315.06 h38.75
  text "Hasl" at 7544.75,7314.11 h38.75
  text "Immersion Gold" at 8846.14,7313.15 h38.75
  text "Hasl Lead Free" at 7543.16,7175.02 h38.75
  text "Immersion Tin" at 8222.35,7168.21 h38.75
  text "Immersion Silver" at 8846.58,7167.6 h38.75
  text "Other" at 9625.84,7166.3 h38.75
  text "Angle" at 7912.81,7025.4 h38.75
  text "No" at 10347.45,7023.03 h38.75
  text "Yes" at 7554.92,7022.45 h38.75
  text "30" at 8890.76,7022.25 h38.75
  text "45" at 9652.18,7022.25 h38.75
  text "20" at 8252.57,7021.07 h38.75
  text "Finger Chamfer:" at 6556.33,7014.52 h38.75
  text "Matte Green" at 8836.8,6874.85 h38.75
  text "Blue" at 8259.53,6870.24 h38.75
  text "Other" at 9642.21,6867.87 h38.75
  text "Green" at 7555.38,6865.29 h38.75
  text "Soldermask Colours:" at 6552.66,6862.19 h38.75
  text "Black" at 8874.89,6722.99 h38.75
  text "Other" at 9646.15,6721.81 h38.75
  text "Silk Screen Colours:" at 6551.14,6718.21 h38.75
  text "White" at 7555.38,6716.47 h38.75
  text "Yellow" at 8256.38,6715.12 h38.75
  text "Spell Mode:" at 6545.35,6535.09 h38.75
  text "Open Windows:" at 8730.79,6532.84 h38.75
  text "None" at 9271.35,6531.26 h38.75
  text "V-cut" at 9255.2,6375.75 h38.75
  text "Stamp Hole" at 10226.86,6373.78 h38.75
  text "Bridge" at 8226.66,6368.82 h38.75
  text "Outline Profile:" at 6548.89,6368.55 h38.75
  text "Router" at 7575.68,6364.33 h38.75
  text "Gjb362A-96" at 9254.02,6228.11 h38.75
  text "Other" at 10229.62,6227.32 h38.75
  text "IPCII" at 7583.16,6225.75 h38.75
  text "IPCIII" at 8224.18,6225.07 h38.75
  text "Inspectionstandard:" at 6545.46,6222.82 h38.75
  text "Yes" at 7583.16,6074.57 h38.75
  text "No" at 8229.42,6073.93 h38.75
  text "Compare With IPC File" at 6545.85,6066.67 h38.75
  text "All via (<=0.5mm) must be filled(except open soldermask via)" at 7546.53,5767.82 h38.75
  text "By gerber" at 10219.77,5766.69 h38.75
  text "Via  Technic:" at 6553.84,5757.07 h38.75
  text "(unit:mil)MIN.track :                    MIN.spacing :                 MIN.hole:" at 6549.12,5610.22 h38.75
  text "4.5mil" at 7295.23,5606.49 h38.75
  text "10mil\18mil" at 9577.74,5606.21 h38.75
  text "4.4mil" at 8623.74,5605.21 h38.75
  text "Pressfit holes: The tolerance of                 is+/-0.05mm" at 8038.41,5464.33 h38.75
  text "0.6mm" at 9386.12,5462.02 h38.75
  text "Bow and Twist Tolerance:<=0.75%" at 6545.91,5461.24 h38.75
  text "1.  STACKING (dielectric thickness can be adjusted beween +/-2mil,but don,t less than 3.5mil; if inspection is Gjb362A" at 6643.12,5212.8 h32.81
  text "than don,t less than 4mil.)" at 6643.12,5112.8 h32.81
  text "2.  Control Impedance (track width can be adjusted +/-0.5mil , but don,t less than 4mil.)" at 6643.12,5012.8 h32.81
  text "TOP" at 10257.67,3442.05 h39.27
  text "Hoz+Plating" at 9723.72,3440.26 h38.75
  text "mil" at 7051.77,3331.21 h38.75
  text "pp" at 7631.3,3331.21 h39.27
  text "1oz" at 9756.87,3223.9 h39.27
  text "PWR02" at 10257.67,3222.37 h39.27
  text "mil" at 7051.77,3111.52 h38.75
  text "Core" at 7631.3,3111.52 h39.27
  text "1oz" at 9756.87,3004.21 h39.27
  text "ART03" at 10257.67,3002.68 h39.27
  text "pp" at 7671.3,2896.21 h39.27
  text "mil" at 7051.77,2891.84 h38.75
  text "1oz" at 9756.87,2784.53 h39.27
  text "ART04" at 10257.67,2783 h39.27
  text "mil" at 7051.77,2672.15 h38.75
  text "Core" at 7631.3,2672.15 h39.27
  text "1oz" at 9756.87,2564.84 h39.27
  text "GND05" at 10257.67,2563.31 h39.27
  text "pp" at 7651.3,2466.21 h39.27
  text "mil" at 7051.77,2452.47 h38.75
  text "BOTTOM" at 10257.67,2343.62 h39.27
  text "Hoz+Plating" at 9731.57,2339.41 h38.75
  text "ref layer" at 9491.14,-682.75 h32.81
  text "+/-10%" at 8810.02,-799.97 h38.75
  text "L1/L6" at 6902.57,-805.88 h39.27
  text "5.0" at 7557.93,-806.24 h39.27
  text "L2/5" at 9462.35,-807.02 h39.27
  text "50.00" at 8202.84,-809.39 h39.27
  text "+/-10%" at 8810.02,-909.81 h38.75
  text "L3/L4" at 6902.57,-915.72 h39.27
  text "4.0" at 7557.93,-916.08 h39.27
  text "L2&5" at 9462.35,-916.87 h39.27
  text "50.00" at 8202.84,-919.23 h39.27
  text "ref layer" at 9513.51,-2769.77 h32.81
  text "4.0/5.0" at 7509.96,-2886.27 h39.27
  text "+/-10%" at 8810.02,-2886.98 h38.75
  text "L2/5" at 9428.43,-2887.06 h39.27
  text "100.00" at 8135,-2889.42 h39.27
  text "L1/6" at 6899.41,-2895.73 h39.27
  text "+/-10%" at 8810.02,-2996.82 h38.75
  text "L2&5" at 9428.43,-2996.9 h39.27
  text "4.5/6.0" at 7509.96,-2997.89 h39.27
  text "100.00" at 8135,-2999.27 h39.27
  text "L3/L4" at 6899.41,-3005.57 h39.27
  text "L1/6" at 6914.41,-3105.73 h39.27
  text "5.0/5.0" at 7509.96,-3109.5 h39.27
  text "90" at 8135,-3114.42 h39.27
  text "+/-10%" at 8810.02,-3116.98 h38.75
  text "L2/5" at 9428.43,-3117.06 h39.27
  text "L3/L4" at 6914.41,-3215.57 h39.27
  text "5.5/6.0" at 7509.96,-3221.12 h39.27
  text "90" at 8135,-3224.27 h39.27
  text "+/-10%" at 8810.02,-3226.82 h38.75
  text "L2&5" at 9428.43,-3226.9 h39.27
  text "Note:If etch layer don't have  above impedance track pls ignore" at 6573.26,-4142.05 h51.67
